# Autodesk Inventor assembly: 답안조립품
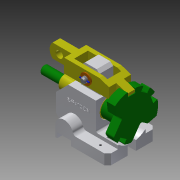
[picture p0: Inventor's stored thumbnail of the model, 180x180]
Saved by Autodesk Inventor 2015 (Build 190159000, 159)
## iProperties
Created: 2016-11
Part Number: 답안조립품
Document SubType Name: Assembly
Designer: LineLG02
Author: LineLG02
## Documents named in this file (8)
- C:\Users\LineLG02\Desktop\461107V1023\답안조립품.iam
- C:\Users\LineLG02\Desktop\461107V1023\본체.ipt
- C:\Users\LineLG02\Desktop\461107V1023\부시.ipt
- C:\Users\LineLG02\Desktop\461107V1023\분할대.ipt
- C:\Users\LineLG02\Desktop\461107V1023\와셔.ipt
- C:\Users\LineLG02\Desktop\461107V1023\클레비스핀.ipt
- C:\Users\LineLG02\Desktop\461107V1023\원통형핀.ipt
- C:\Users\LineLG02\Desktop\461107V1023\분할축.ipt
